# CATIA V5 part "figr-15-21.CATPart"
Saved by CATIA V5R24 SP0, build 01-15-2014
Part number: Part1
Bounding box of the stored display mesh (mm): x -81.56 to 85.56, y -36.965 to 25.965, z 0 to 42
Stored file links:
  D:\KAVITA\CATIA V5-6R2014 Project_ Kavita\CATIA V5-6R2014_partfiles\Partfiles\c15_catia_v5-6r2014_prt\figr-15-21.CATPart
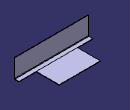
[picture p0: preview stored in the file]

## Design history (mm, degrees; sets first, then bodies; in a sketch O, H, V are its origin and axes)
SheetMetalParameters1: Thickness 1, BendRadius 1, KFactor 0.325257 {= log(min(100,max(20*SheetMetalParameters1.BendRadius,SheetMetalParameters1.Thickness)/SheetMetalParameters1.Thickness))/log(100)/2}, ReliefRadialLength 1, ReliefAxialLength 2, MinimumBendRadius 0
Body1 (main body)
  Sketch1 on xy-plane, origin (0, 0, 0), H (1, 0, 0), V (0, 1, 0)
    line L1 (-46.5596, 25.9646) -> (46.5596, 25.9646)
    line L2 (46.5596, 25.9646) -> (46.5596, -25.9646)
    line L3 (46.5596, -25.9646) -> (-46.5596, -25.9646)
    line L4 (-46.5596, -25.9646) -> (-46.5596, 25.9646)
    horizontal: L1 H, L3 H
    vertical: L2 V, L4 V
    symmetry: L1 L3 H, L4 L2 V
  Wall1: Thickness 1, Profile Sketch1
  d_NewWallOnEdge1: NewWallOnEdge_Edge edge [face of Wall1 | face of Wall1], KFacteur 0.325257 {= log(min(100,max(20*d_NewWallOnEdge1.Radius,SheetMetalParameters1.Thickness)/SheetMetalParameters1.Thickness))/log(100)/2}, NewWallOnEdge_Length 42, NewWallOnEdge_HeightLimitOffset 0, NewWallOnEdge_WidthOffset1 39, NewWallOnEdge_WidthOffset2 35, NewWallOnEdge_Angle 90, NewWallOnEdge_BendRadiusValue 1 {= SheetMetalParameters1.BendRadius}, NewWallOnEdge_BendTable SheetMetalParameters1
